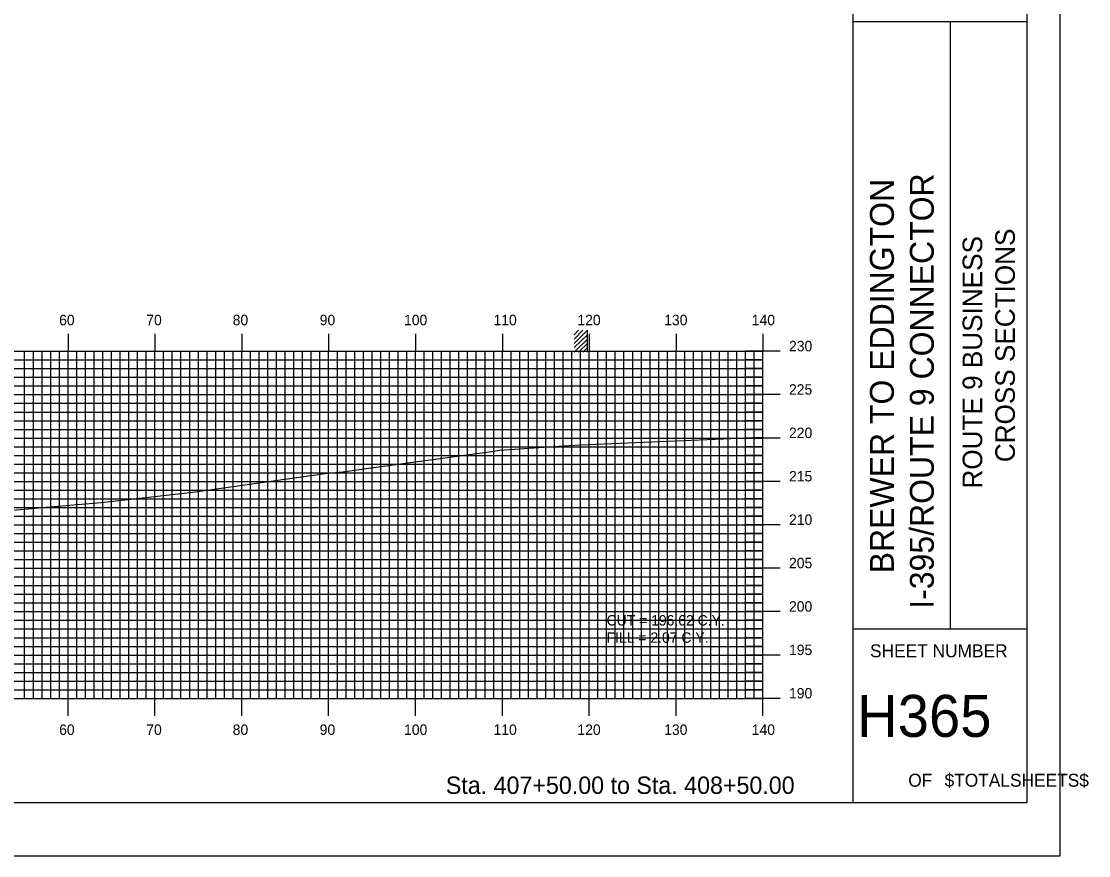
# Model space of a CAD drawing. Extents: x 852529 to 852872, y 364785 to 365005.
# Drawn here: x 852749.3 to 852872.2, y 364785.1 to 364881.2 of the extents above; entities that cross this region are included whole.
import ezdxf

# ---------------------------------------------------------------- set-up
doc = ezdxf.new("R2010")
doc.units = 0
for name, color, linetype in [('BORDER', 7, 'Continuous'), ('D_Text_Standard', 7, 'Continuous'), ('H_V ANNOTATION', 7, 'Continuous'), ('M_Buildings_Rooftop', 7, 'Continuous'), ('MAJOR', 7, 'Continuous'), ('MINOR', 7, 'Continuous'), ('PLOT BOUNDARY', 7, 'Continuous'), ('S_Roadway_Centerline', 7, 'Continuous')]:
    doc.layers.add(name, color=color, linetype=linetype)

msp = doc.modelspace()

# ---------------------------------------------------------------- linework, layer by layer
at = {"layer": 'BORDER'}
for p, q in [((852845.13, 364791.23), (852845.13, 365001.23)), ((852845.13, 364881.24), (852865.13, 364881.24)), ((852856.31, 364811.24), (852856.31, 364881.24)), ((852845.13, 364811.24), (852865.13, 364811.24))]:
    msp.add_line(p, q, dxfattribs=at)
msp.add_lwpolyline([(852545.13, 364791.23), (852865.13, 364791.23), (852865.13, 365001.23), (852545.13, 365001.23)], close=True, dxfattribs=at)
at = {"layer": 'M_Buildings_Rooftop'}
for p, q in [((852813.01, 364844.14), (852814.52, 364845.65)), ((852813.01, 364844.64), (852813.99, 364845.65)), ((852813.01, 364845.13), (852813.5, 364845.65)), ((852813.01, 364843.65), (852814.52, 364845.13)), ((852814.52, 364843.13), (852814.52, 364845.65)), ((852813.01, 364843.13), (852814.52, 364844.64)), ((852813.5, 364843.13), (852814.52, 364844.14)), ((852813.99, 364843.13), (852814.52, 364843.65))]:
    msp.add_line(p, q, dxfattribs=at)
at = {"layer": 'MAJOR'}
for p, q in [((852754.73, 364845.24), (852754.73, 364843.23)), ((852764.73, 364845.24), (852764.73, 364843.23)), ((852774.73, 364845.24), (852774.73, 364843.23)), ((852784.73, 364845.24), (852784.73, 364843.23)), ((852794.73, 364845.24), (852794.73, 364843.23)), ((852804.73, 364845.24), (852804.73, 364843.23)), ((852814.73, 364845.24), (852814.73, 364843.23)), ((852824.73, 364845.24), (852824.73, 364843.23)), ((852834.73, 364845.24), (852834.73, 364843.23)), ((852554.73, 364843.23), (852834.73, 364843.23)), ((852554.73, 364843.23), (852834.73, 364843.23)), ((852754.73, 364803.23), (852754.73, 364843.23)), ((852764.73, 364803.23), (852764.73, 364843.23)), ((852774.73, 364803.23), (852774.73, 364843.23)), ((852784.73, 364803.23), (852784.73, 364843.23)), ((852794.73, 364803.23), (852794.73, 364843.23)), ((852804.73, 364803.23), (852804.73, 364843.23)), ((852814.73, 364803.23), (852814.73, 364843.23)), ((852824.73, 364803.23), (852824.73, 364843.23)), ((852836.73, 364843.23), (852832.73, 364843.23)), ((852834.73, 364803.23), (852834.73, 364843.23)), ((852834.73, 364803.23), (852834.73, 364843.23)), ((852554.73, 364838.23), (852834.73, 364838.23)), ((852836.73, 364838.23), (852832.73, 364838.23)), ((852554.73, 364833.23), (852834.73, 364833.23)), ((852836.73, 364833.23), (852832.73, 364833.23)), ((852554.73, 364828.23), (852834.73, 364828.23)), ((852836.73, 364828.23), (852832.73, 364828.23)), ((852554.73, 364823.23), (852834.73, 364823.23)), ((852836.73, 364823.23), (852832.73, 364823.23)), ((852554.73, 364818.23), (852834.73, 364818.23)), ((852836.73, 364818.23), (852832.73, 364818.23)), ((852554.73, 364813.23), (852834.73, 364813.23)), ((852836.73, 364813.23), (852832.73, 364813.23)), ((852554.73, 364808.23), (852834.73, 364808.23)), ((852836.73, 364808.23), (852832.73, 364808.23)), ((852554.73, 364803.23), (852834.73, 364803.23)), ((852554.73, 364803.23), (852834.73, 364803.23)), ((852754.73, 364801.23), (852754.73, 364803.23)), ((852764.73, 364801.23), (852764.73, 364803.23)), ((852774.73, 364801.23), (852774.73, 364803.23)), ((852784.73, 364801.23), (852784.73, 364803.23)), ((852794.73, 364801.23), (852794.73, 364803.23)), ((852804.73, 364801.23), (852804.73, 364803.23)), ((852814.73, 364801.23), (852814.73, 364803.23)), ((852824.73, 364801.23), (852824.73, 364803.23)), ((852836.73, 364803.23), (852832.73, 364803.23)), ((852834.73, 364801.23), (852834.73, 364803.23))]:
    msp.add_line(p, q, dxfattribs=at)
at = {"layer": 'MINOR'}
for p, q in [((852554.73, 364842.23), (852834.73, 364842.23)), ((852749.73, 364803.23), (852749.73, 364843.23)), ((852750.73, 364803.23), (852750.73, 364843.23)), ((852751.73, 364803.23), (852751.73, 364843.23)), ((852752.73, 364803.23), (852752.73, 364843.23)), ((852753.73, 364803.23), (852753.73, 364843.23)), ((852755.73, 364803.23), (852755.73, 364843.23)), ((852756.73, 364803.23), (852756.73, 364843.23)), ((852757.73, 364803.23), (852757.73, 364843.23)), ((852758.73, 364803.23), (852758.73, 364843.23)), ((852759.73, 364803.23), (852759.73, 364843.23)), ((852760.73, 364803.23), (852760.73, 364843.23)), ((852761.73, 364803.23), (852761.73, 364843.23)), ((852762.73, 364803.23), (852762.73, 364843.23)), ((852763.73, 364803.23), (852763.73, 364843.23)), ((852765.73, 364803.23), (852765.73, 364843.23)), ((852766.73, 364803.23), (852766.73, 364843.23)), ((852767.73, 364803.23), (852767.73, 364843.23)), ((852768.73, 364803.23), (852768.73, 364843.23)), ((852769.73, 364803.23), (852769.73, 364843.23)), ((852770.73, 364803.23), (852770.73, 364843.23)), ((852771.73, 364803.23), (852771.73, 364843.23)), ((852772.73, 364803.23), (852772.73, 364843.23)), ((852773.73, 364803.23), (852773.73, 364843.23)), ((852775.73, 364803.23), (852775.73, 364843.23)), ((852776.73, 364803.23), (852776.73, 364843.23)), ((852777.73, 364803.23), (852777.73, 364843.23)), ((852778.73, 364803.23), (852778.73, 364843.23)), ((852779.73, 364803.23), (852779.73, 364843.23)), ((852780.73, 364803.23), (852780.73, 364843.23)), ((852781.73, 364803.23), (852781.73, 364843.23)), ((852782.73, 364803.23), (852782.73, 364843.23)), ((852783.73, 364803.23), (852783.73, 364843.23)), ((852785.73, 364803.23), (852785.73, 364843.23)), ((852786.73, 364803.23), (852786.73, 364843.23)), ((852787.73, 364803.23), (852787.73, 364843.23)), ((852788.73, 364803.23), (852788.73, 364843.23)), ((852789.73, 364803.23), (852789.73, 364843.23)), ((852790.73, 364803.23), (852790.73, 364843.23)), ((852791.73, 364803.23), (852791.73, 364843.23)), ((852792.73, 364803.23), (852792.73, 364843.23)), ((852793.73, 364803.23), (852793.73, 364843.23)), ((852795.73, 364803.23), (852795.73, 364843.23)), ((852796.73, 364803.23), (852796.73, 364843.23)), ((852797.73, 364803.23), (852797.73, 364843.23)), ((852798.73, 364803.23), (852798.73, 364843.23)), ((852799.73, 364803.23), (852799.73, 364843.23)), ((852800.73, 364803.23), (852800.73, 364843.23)), ((852801.73, 364803.23), (852801.73, 364843.23)), ((852802.73, 364803.23), (852802.73, 364843.23)), ((852803.73, 364803.23), (852803.73, 364843.23)), ((852805.73, 364803.23), (852805.73, 364843.23)), ((852806.73, 364803.23), (852806.73, 364843.23)), ((852807.73, 364803.23), (852807.73, 364843.23)), ((852808.73, 364803.23), (852808.73, 364843.23)), ((852809.73, 364803.23), (852809.73, 364843.23)), ((852810.73, 364803.23), (852810.73, 364843.23)), ((852811.73, 364803.23), (852811.73, 364843.23)), ((852812.73, 364803.23), (852812.73, 364843.23)), ((852813.73, 364803.23), (852813.73, 364843.23)), ((852815.73, 364803.23), (852815.73, 364843.23)), ((852816.73, 364803.23), (852816.73, 364843.23)), ((852817.73, 364803.23), (852817.73, 364843.23)), ((852818.73, 364803.23), (852818.73, 364843.23)), ((852819.73, 364803.23), (852819.73, 364843.23)), ((852820.73, 364803.23), (852820.73, 364843.23)), ((852821.73, 364803.23), (852821.73, 364843.23)), ((852822.73, 364803.23), (852822.73, 364843.23)), ((852823.73, 364803.23), (852823.73, 364843.23)), ((852825.73, 364803.23), (852825.73, 364843.23)), ((852826.73, 364803.23), (852826.73, 364843.23)), ((852827.73, 364803.23), (852827.73, 364843.23)), ((852828.73, 364803.23), (852828.73, 364843.23)), ((852829.73, 364803.23), (852829.73, 364843.23)), ((852830.73, 364803.23), (852830.73, 364843.23)), ((852831.73, 364803.23), (852831.73, 364843.23)), ((852832.73, 364803.23), (852832.73, 364843.23)), ((852834.73, 364842.23), (852832.73, 364842.23)), ((852833.73, 364803.23), (852833.73, 364843.23)), ((852554.73, 364841.23), (852834.73, 364841.23)), ((852834.73, 364841.23), (852832.73, 364841.23)), ((852554.73, 364840.23), (852834.73, 364840.23)), ((852834.73, 364840.23), (852832.73, 364840.23)), ((852554.73, 364839.23), (852834.73, 364839.23)), ((852834.73, 364839.23), (852832.73, 364839.23)), ((852554.73, 364837.23), (852834.73, 364837.23)), ((852554.73, 364836.23), (852834.73, 364836.23)), ((852834.73, 364837.23), (852832.73, 364837.23)), ((852834.73, 364836.23), (852832.73, 364836.23)), ((852554.73, 364835.23), (852834.73, 364835.23)), ((852834.73, 364835.23), (852832.73, 364835.23)), ((852554.73, 364834.23), (852834.73, 364834.23)), ((852834.73, 364834.23), (852832.73, 364834.23)), ((852554.73, 364832.23), (852834.73, 364832.23)), ((852554.73, 364831.23), (852834.73, 364831.23)), ((852834.73, 364832.23), (852832.73, 364832.23)), ((852834.73, 364831.23), (852832.73, 364831.23)), ((852554.73, 364830.23), (852834.73, 364830.23)), ((852834.73, 364830.23), (852832.73, 364830.23)), ((852554.73, 364829.23), (852834.73, 364829.23)), ((852834.73, 364829.23), (852832.73, 364829.23)), ((852554.73, 364827.23), (852834.73, 364827.23)), ((852554.73, 364826.23), (852834.73, 364826.23)), ((852834.73, 364827.23), (852832.73, 364827.23)), ((852834.73, 364826.23), (852832.73, 364826.23)), ((852554.73, 364825.23), (852834.73, 364825.23)), ((852834.73, 364825.23), (852832.73, 364825.23)), ((852554.73, 364824.23), (852834.73, 364824.23)), ((852834.73, 364824.23), (852832.73, 364824.23)), ((852554.73, 364822.23), (852834.73, 364822.23)), ((852834.73, 364822.23), (852832.73, 364822.23)), ((852554.73, 364821.23), (852834.73, 364821.23)), ((852554.73, 364820.23), (852834.73, 364820.23)), ((852834.73, 364821.23), (852832.73, 364821.23)), ((852834.73, 364820.23), (852832.73, 364820.23)), ((852554.73, 364819.23), (852834.73, 364819.23)), ((852834.73, 364819.23), (852832.73, 364819.23)), ((852554.73, 364817.23), (852834.73, 364817.23)), ((852834.73, 364817.23), (852832.73, 364817.23)), ((852554.73, 364816.23), (852834.73, 364816.23)), ((852554.73, 364815.23), (852834.73, 364815.23)), ((852834.73, 364816.23), (852832.73, 364816.23)), ((852834.73, 364815.23), (852832.73, 364815.23)), ((852554.73, 364814.23), (852834.73, 364814.23)), ((852834.73, 364814.23), (852832.73, 364814.23)), ((852554.73, 364812.23), (852834.73, 364812.23)), ((852834.73, 364812.23), (852832.73, 364812.23)), ((852554.73, 364811.23), (852834.73, 364811.23)), ((852554.73, 364810.23), (852834.73, 364810.23)), ((852834.73, 364811.23), (852832.73, 364811.23)), ((852834.73, 364810.23), (852832.73, 364810.23)), ((852554.73, 364809.23), (852834.73, 364809.23)), ((852834.73, 364809.23), (852832.73, 364809.23)), ((852554.73, 364807.23), (852834.73, 364807.23)), ((852834.73, 364807.23), (852832.73, 364807.23)), ((852554.73, 364806.23), (852834.73, 364806.23)), ((852834.73, 364806.23), (852832.73, 364806.23)), ((852554.73, 364805.23), (852834.73, 364805.23)), ((852554.73, 364804.23), (852834.73, 364804.23)), ((852834.73, 364805.23), (852832.73, 364805.23)), ((852834.73, 364804.23), (852832.73, 364804.23))]:
    msp.add_line(p, q, dxfattribs=at)
at = {"layer": 'PLOT BOUNDARY'}
msp.add_lwpolyline([(852528.94, 364785.11), (852868.94, 364785.11), (852868.94, 365005.11), (852528.94, 365005.11)], close=True, dxfattribs=at)
at = {"layer": 'S_Roadway_Centerline'}
msp.add_lwpolyline([(852743.83, 364824.53), (852750.15, 364825.09), (852752.22, 364825.26), (852758.53, 364825.81), (852769.09, 364826.99), (852784.33, 364829.13), (852786.31, 364829.35), (852790.48, 364829.9), (852803.8, 364831.72), (852804.39, 364831.85), (852810.61, 364832.26), (852813.69, 364832.44), (852834.73, 364833.32)], dxfattribs=at)

# ---------------------------------------------------------------- texts
at = {"layer": 'BORDER'}
for s, height, p in [('I-395/ROUTE 9 CONNECTOR', 2.7557, (852854.4, 364813.56)), ('BREWER TO EDDINGTON', 2.7557, (852849.8, 364817.64)), ('CROSS SECTIONS', 2.25, (852863.73, 364830.45)), ('ROUTE 9 BUSINESS', 2.25, (852859.97, 364827.41))]:
    msp.add_text(s, height=height, rotation=90, dxfattribs=at).set_placement(p)
for s, height, p in [('SHEET NUMBER', 1.4905, (852847.06, 364807.97)), ('H365', 4.839, (852845.57, 364798.8)), ('OF', 1.491, (852851.46, 364793.06)), ('$TOTALSHEETS$', 1.4905, (852855.64, 364793.06))]:
    msp.add_text(s, height=height, dxfattribs=at).set_placement(p)
at = {"layer": 'D_Text_Standard'}
for s, p in [('CUT = 196.62 C.Y.', (852816.73, 364811.63)), ('FILL = 2.07 C.Y.', (852816.73, 364809.64))]:
    msp.add_text(s, height=1.2, dxfattribs=at).set_placement(p)
at = {"layer": 'H_V ANNOTATION'}
for s, height, p in [('60', 1.2, (852753.7, 364846.23)), ('70', 1.2, (852763.73, 364846.23)), ('80', 1.2, (852773.68, 364846.23)), ('90', 1.2, (852783.7, 364846.23)), ('100', 1.2, (852793.41, 364846.23)), ('110', 1.2, (852803.71, 364846.23)), ('120', 1.2, (852813.37, 364846.23)), ('130', 1.2, (852823.36, 364846.23)), ('140', 1.2, (852833.44, 364846.23)), ('230', 1.2, (852837.73, 364843.23)), ('225', 1.2, (852837.73, 364838.23)), ('220', 1.2, (852837.73, 364833.23)), ('215', 1.2, (852837.73, 364828.23)), ('210', 1.2, (852837.73, 364823.23)), ('205', 1.2, (852837.73, 364818.23)), ('200', 1.2, (852837.73, 364813.23)), ('195', 1.2, (852837.73, 364808.23)), ('190', 1.2, (852837.73, 364803.23)), ('60', 1.2, (852753.7, 364799.03)), ('70', 1.2, (852763.73, 364799.03)), ('80', 1.2, (852773.68, 364799.03)), ('90', 1.2, (852783.7, 364799.03)), ('100', 1.2, (852793.41, 364799.03)), ('110', 1.2, (852803.71, 364799.03)), ('120', 1.2, (852813.37, 364799.03)), ('130', 1.2, (852823.36, 364799.03)), ('140', 1.2, (852833.44, 364799.03)), ('Sta. 407+50.00 to Sta. 408+50.00', 2.0004, (852798.22, 364792.23))]:
    msp.add_text(s, height=height, dxfattribs=at).set_placement(p)

doc.saveas('drawing.dxf')
